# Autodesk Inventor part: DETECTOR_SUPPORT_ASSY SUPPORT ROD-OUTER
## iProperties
Shininess: 64.0
Length Units: 11272
Angle Units: 11279
Time Units: 11290
Mass Units: 11286
Length Display Precision: 3
Angle Display Precision: 2
Compacted: True
Part Number: DETECTOR_SUPPORT_ASSY SUPPORT ROD-OUTER
Document SubType Name: Modeling
Created: 2004-08
Designer: John Blackburn
Material: ALUMINUM
Manufacturer: Standard
Standards Organization: Custom
Density: 0.0
Volumn: 0.0
Area: 0.0
PropertySet Name: Model Information
Control State: 0
Master: False
Checked Out: False
Author: John Blackburn
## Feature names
1. ExtrusionBlind1
